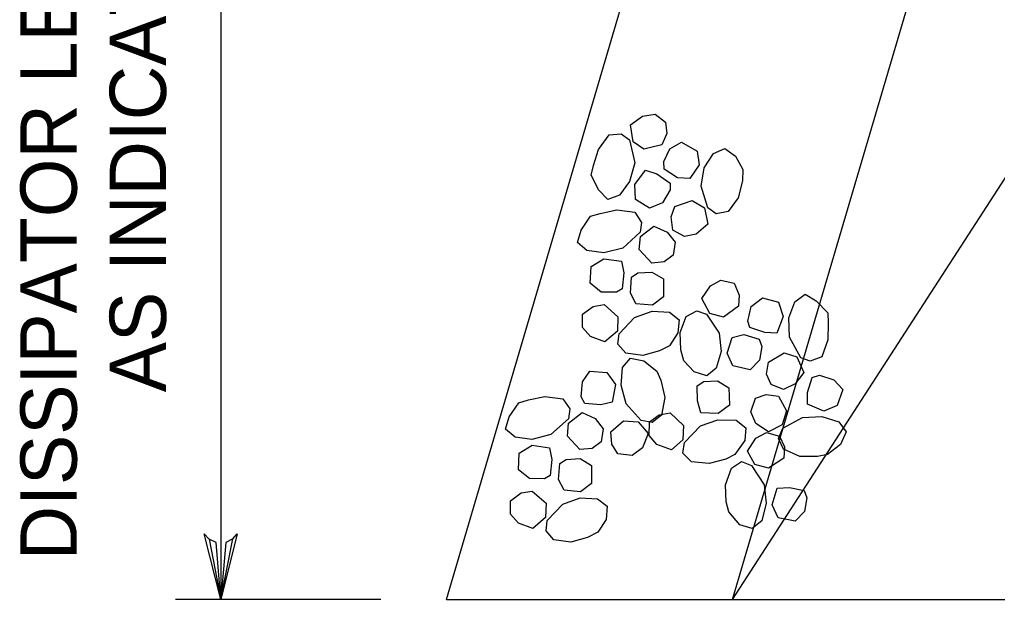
# Model space of a CAD drawing. Extents: x 636462 to 639890, y 299944 to 300538.
# Drawn here: x 637624.9 to 637676.9, y 300172.3 to 300203.1 of the extents above; entities that cross this region are included whole.
import ezdxf

# ---------------------------------------------------------------- set-up
doc = ezdxf.new("R2010")
doc.units = 0
doc.layers.add('Default', color=7, linetype='Continuous')

msp = doc.modelspace()

# ---------------------------------------------------------------- linework, layer by layer
at = {"layer": 'Default'}
for p, q in [((637635.644, 300227.091), (637635.644, 300172.26)), ((637647.635, 300172.26), (637663.777, 300227.091)), ((637662.855, 300172.26), (637698.264, 300227.091)), ((637662.855, 300172.26), (637678.997, 300227.091)), ((637658.054, 300197.981), (637658.728, 300198.086)), ((637658.728, 300198.086), (637659.28, 300197.665)), ((637657.432, 300197.527), (637658.054, 300197.981)), ((637657.563, 300196.629), (637657.432, 300197.527)), ((637659.28, 300197.665), (637659.359, 300197.065)), ((637656.287, 300196.995), (637656.936, 300197.049)), ((637656.936, 300197.049), (637657.363, 300196.727)), ((637659.359, 300197.065), (637659.088, 300196.464)), ((637655.717, 300196.216), (637656.287, 300196.995)), ((637657.363, 300196.727), (637657.646, 300195.505)), ((637658.141, 300196.233), (637657.563, 300196.629)), ((637659.515, 300196.242), (637660.137, 300196.596)), ((637660.137, 300196.596), (637660.965, 300196.127)), ((637655.448, 300195.365), (637655.717, 300196.216)), ((637659.088, 300196.464), (637658.141, 300196.233)), ((637659.194, 300195.565), (637659.515, 300196.242)), ((637660.965, 300196.127), (637661.069, 300195.403)), ((637661.345, 300195.23), (637661.84, 300196.008)), ((637661.84, 300196.008), (637662.438, 300196.262)), ((637662.438, 300196.262), (637663.015, 300195.866)), ((637657.646, 300195.505), (637657.378, 300194.504)), ((637659.222, 300195.166), (637659.194, 300195.565)), ((637663.015, 300195.866), (637663.395, 300195.144)), ((637655.327, 300194.84), (637655.448, 300195.365)), ((637657.654, 300194.356), (637658.223, 300195.109)), ((637658.223, 300195.109), (637658.824, 300194.913)), ((637659.925, 300194.696), (637659.222, 300195.166)), ((637661.069, 300195.403), (637660.575, 300194.675)), ((637661.177, 300194.254), (637661.345, 300195.23)), ((637663.395, 300195.144), (637663.374, 300194.544)), ((637655.732, 300194.043), (637655.327, 300194.84)), ((637657.378, 300194.504), (637656.833, 300193.776)), ((637658.824, 300194.913), (637659.527, 300194.418)), ((637659.527, 300194.418), (637659.529, 300194.068)), ((637660.575, 300194.675), (637659.925, 300194.696)), ((637663.374, 300194.544), (637663.155, 300193.643)), ((637656.21, 300193.546), (637655.732, 300194.043)), ((637657.684, 300193.556), (637657.654, 300194.356)), ((637659.529, 300194.068), (637659.134, 300193.366)), ((637661.534, 300193.108), (637661.177, 300194.254)), ((637656.833, 300193.776), (637656.21, 300193.546)), ((637658.437, 300193.087), (637657.684, 300193.556)), ((637659.134, 300193.366), (637658.437, 300193.087)), ((637659.785, 300193.171), (637660.707, 300193.502)), ((637660.707, 300193.502), (637661.36, 300193.106)), ((637663.155, 300193.643), (637662.61, 300192.915)), ((637655.816, 300192.812), (637656.691, 300192.992)), ((637656.691, 300192.992), (637657.648, 300192.875)), ((637657.648, 300192.875), (637658.012, 300192.335)), ((637659.589, 300192.62), (637659.785, 300193.171)), ((637661.36, 300193.106), (637661.54, 300192.233)), ((637661.986, 300192.786), (637661.534, 300193.108)), ((637662.61, 300192.915), (637661.986, 300192.786)), ((637654.801, 300191.919), (637655.299, 300192.662)), ((637655.299, 300192.662), (637655.816, 300192.812)), ((637658.012, 300192.335), (637657.939, 300191.805)), ((637659.669, 300191.921), (637659.589, 300192.62)), ((637654.6, 300191.26), (637654.801, 300191.919)), ((637657.939, 300191.805), (637657.01, 300190.962)), ((637657.951, 300191.582), (637658.672, 300192.134)), ((637658.672, 300192.134), (637659.371, 300191.813)), ((637659.371, 300191.813), (637659.791, 300191.276)), ((637660.296, 300191.575), (637659.669, 300191.921)), ((637661.54, 300192.233), (637660.919, 300191.704)), ((637657.887, 300190.885), (637657.951, 300191.582)), ((637660.919, 300191.704), (637660.296, 300191.575)), ((637655.104, 300190.828), (637654.6, 300191.26)), ((637656.006, 300190.707), (637655.104, 300190.828)), ((637657.01, 300190.962), (637656.006, 300190.707)), ((637658.551, 300190.17), (637657.887, 300190.885)), ((637659.791, 300191.276), (637659.693, 300190.588)), ((637655.328, 300189.978), (637656.011, 300190.394)), ((637656.011, 300190.394), (637656.947, 300190.265)), ((637656.947, 300190.265), (637657.069, 300189.644)), ((637659.693, 300190.588), (637659.209, 300190.227)), ((637655.285, 300189.092), (637655.328, 300189.978)), ((637659.209, 300190.227), (637658.551, 300190.17)), ((637657.069, 300189.644), (637656.98, 300188.789)), ((637657.416, 300188.577), (637657.483, 300189.42)), ((637657.483, 300189.42), (637657.819, 300189.639)), ((637657.819, 300189.639), (637658.566, 300189.69)), ((637658.566, 300189.69), (637659.178, 300189.319)), ((637659.178, 300189.319), (637659.172, 300188.368)), ((637661.67, 300188.96), (637662.233, 300189.258)), ((637662.233, 300189.258), (637662.931, 300189.101)), ((637655.87, 300188.619), (637655.285, 300189.092)), ((637656.98, 300188.789), (637656.675, 300188.617)), ((637661.221, 300188.279), (637661.67, 300188.96)), ((637662.931, 300189.101), (637663.203, 300188.452)), ((637656.675, 300188.617), (637655.87, 300188.619)), ((637657.715, 300188), (637657.416, 300188.577)), ((637659.172, 300188.368), (637658.592, 300187.923)), ((637661.638, 300187.491), (637661.221, 300188.279)), ((637663.203, 300188.452), (637663.168, 300187.868)), ((637663.848, 300187.862), (637664.44, 300188.325)), ((637664.44, 300188.325), (637665.293, 300188.084)), ((637666.172, 300188.111), (637666.706, 300188.505)), ((637666.706, 300188.505), (637667.304, 300188.162)), ((637654.868, 300187.447), (637655.44, 300187.858)), ((637655.44, 300187.858), (637656.016, 300187.955)), ((637656.016, 300187.955), (637656.755, 300187.312)), ((637658.592, 300187.923), (637657.715, 300188)), ((637663.168, 300187.868), (637662.375, 300187.293)), ((637663.664, 300187.078), (637663.848, 300187.862)), ((637665.293, 300188.084), (637665.546, 300187.325)), ((637665.852, 300187.26), (637666.172, 300188.111)), ((637667.304, 300188.162), (637667.915, 300187.51)), ((637654.873, 300186.732), (637654.868, 300187.447)), ((637656.755, 300187.312), (637656.728, 300186.55)), ((637656.815, 300186.398), (637657.641, 300187.269)), ((637657.641, 300187.269), (637658.575, 300187.598)), ((637658.575, 300187.598), (637659.495, 300187.546)), ((637659.495, 300187.546), (637660.009, 300187.148)), ((637660.009, 300187.148), (637659.945, 300186.451)), ((637660.064, 300186.475), (637660.384, 300187.326)), ((637660.384, 300187.326), (637660.947, 300187.624)), ((637660.947, 300187.624), (637661.471, 300187.441)), ((637661.471, 300187.441), (637662.134, 300186.439)), ((637662.375, 300187.293), (637661.638, 300187.491)), ((637665.546, 300187.325), (637665.209, 300186.443)), ((637665.874, 300186.224), (637665.852, 300187.26)), ((637667.915, 300187.51), (637667.945, 300186.971)), ((637655.29, 300186.25), (637654.873, 300186.732)), ((637663.764, 300186.743), (637663.664, 300187.078)), ((637664.577, 300186.463), (637663.764, 300186.743)), ((637667.945, 300186.971), (637667.924, 300186.079)), ((637656.054, 300185.966), (637655.29, 300186.25)), ((637656.728, 300186.55), (637656.054, 300185.966)), ((637656.754, 300185.846), (637656.815, 300186.398)), ((637659.945, 300186.451), (637659.5, 300185.767)), ((637660.105, 300185.548), (637660.064, 300186.475)), ((637662.134, 300186.439), (637662.244, 300185.456)), ((637662.558, 300185.367), (637662.83, 300186.204)), ((637662.83, 300186.204), (637663.459, 300186.365)), ((637663.459, 300186.365), (637664.265, 300186.11)), ((637664.265, 300186.11), (637664.403, 300185.734)), ((637665.209, 300186.443), (637664.577, 300186.463)), ((637666.487, 300185.129), (637665.874, 300186.224)), ((637657.171, 300185.365), (637656.754, 300185.846)), ((637659.5, 300185.767), (637658.966, 300185.493)), ((637664.403, 300185.734), (637664.285, 300184.995)), ((637667.924, 300186.079), (637667.595, 300185.172)), ((637656.995, 300184.601), (637657.427, 300185.105)), ((637658.073, 300185.244), (637657.171, 300185.365)), ((637657.427, 300185.105), (637658.14, 300184.963)), ((637658.966, 300185.493), (637658.073, 300185.244)), ((637660.252, 300184.967), (637660.105, 300185.548)), ((637662.244, 300185.456), (637661.987, 300184.571)), ((637662.86, 300184.701), (637662.558, 300185.367)), ((637664.756, 300184.9), (637665.602, 300185.387)), ((637665.602, 300185.387), (637666.266, 300185.168)), ((637666.266, 300185.168), (637666.643, 300184.342)), ((637666.986, 300184.939), (637666.487, 300185.129)), ((637667.595, 300185.172), (637666.986, 300184.939)), ((637656.921, 300183.668), (637656.995, 300184.601)), ((637658.14, 300184.963), (637658.829, 300184.407)), ((637660.818, 300184.379), (637660.252, 300184.967)), ((637661.987, 300184.571), (637661.483, 300184.16)), ((637663.786, 300184.481), (637662.86, 300184.701)), ((637664.285, 300184.995), (637663.786, 300184.481)), ((637664.664, 300184.247), (637664.756, 300184.9)), ((637654.864, 300183.851), (637655.259, 300184.42)), ((637655.259, 300184.42), (637656.17, 300184.334)), ((637656.17, 300184.334), (637656.618, 300183.697)), ((637658.829, 300184.407), (637659.045, 300183.926)), ((637661.483, 300184.16), (637660.818, 300184.379)), ((637664.907, 300183.694), (637664.664, 300184.247)), ((637666.643, 300184.342), (637666.173, 300183.732)), ((637666.83, 300183.276), (637667.085, 300184.082)), ((637667.085, 300184.082), (637667.468, 300184.196)), ((637667.468, 300184.196), (637668.243, 300183.958)), ((637654.806, 300183.042), (637654.864, 300183.851)), ((637656.618, 300183.697), (637656.454, 300182.771)), ((637657.197, 300182.676), (637656.921, 300183.668)), ((637659.045, 300183.926), (637659.25, 300183.008)), ((637660.962, 300183.635), (637661.319, 300183.867)), ((637660.981, 300182.842), (637660.962, 300183.635)), ((637661.319, 300183.867), (637662.044, 300183.905)), ((637662.044, 300183.905), (637662.657, 300183.534)), ((637662.657, 300183.534), (637662.694, 300182.608)), ((637665.555, 300183.444), (637664.907, 300183.694)), ((637666.173, 300183.732), (637665.555, 300183.444)), ((637668.243, 300183.958), (637668.709, 300183.445)), ((637651.995, 300182.883), (637652.869, 300183.063)), ((637652.869, 300183.063), (637653.826, 300182.946)), ((637655.003, 300182.695), (637654.806, 300183.042)), ((637659.25, 300183.008), (637659.064, 300182.07)), ((637663.825, 300182.251), (637664.077, 300182.978)), ((637664.077, 300182.978), (637664.645, 300183.173)), ((637664.645, 300183.173), (637665.298, 300183.081)), ((637665.298, 300183.081), (637665.715, 300182.293)), ((637666.833, 300182.652), (637666.83, 300183.276)), ((637668.709, 300183.445), (637668.42, 300182.577)), ((637650.979, 300181.99), (637651.477, 300182.733)), ((637651.477, 300182.733), (637651.995, 300182.883)), ((637653.826, 300182.946), (637654.191, 300182.406)), ((637655.846, 300182.627), (637655.003, 300182.695)), ((637656.454, 300182.771), (637655.846, 300182.627)), ((637657.994, 300181.778), (637657.197, 300182.676)), ((637661.172, 300182.203), (637660.981, 300182.842)), ((637662.694, 300182.608), (637662.092, 300182.151)), ((637667.699, 300182.284), (637666.833, 300182.652)), ((637668.42, 300182.577), (637667.699, 300182.284)), ((637650.779, 300181.331), (637650.979, 300181.99)), ((637654.191, 300182.406), (637654.118, 300181.876)), ((637654.13, 300181.653), (637654.85, 300182.205)), ((637654.85, 300182.205), (637655.549, 300181.884)), ((637658.434, 300181.712), (637658.94, 300182.085)), ((637659.064, 300182.07), (637658.57, 300181.674)), ((637658.94, 300182.085), (637659.539, 300182.195)), ((637659.539, 300182.195), (637660.234, 300181.527)), ((637662.092, 300182.151), (637661.172, 300182.203)), ((637664.089, 300181.626), (637663.825, 300182.251)), ((637665.715, 300182.293), (637665.494, 300181.549)), ((637665.52, 300181.374), (637666.574, 300181.949)), ((637666.574, 300181.949), (637667.603, 300181.994)), ((637667.603, 300181.994), (637668.495, 300181.713)), ((637654.118, 300181.876), (637653.189, 300181.033)), ((637654.066, 300180.956), (637654.13, 300181.653)), ((637655.549, 300181.884), (637655.969, 300181.347)), ((637656.381, 300181.179), (637657.055, 300181.762)), ((637657.055, 300181.762), (637657.83, 300181.714)), ((637657.83, 300181.714), (637658.355, 300181.092)), ((637658.57, 300181.674), (637657.994, 300181.778)), ((637658.416, 300180.984), (637658.434, 300181.712)), ((637660.234, 300181.527), (637660.207, 300180.765)), ((637660.293, 300180.613), (637661.142, 300181.497)), ((637661.142, 300181.497), (637662.075, 300181.825)), ((637662.075, 300181.825), (637663.039, 300181.798)), ((637663.039, 300181.798), (637663.552, 300181.4)), ((637664.77, 300181.177), (637664.089, 300181.626)), ((637665.494, 300181.549), (637664.77, 300181.177)), ((637668.495, 300181.713), (637668.889, 300181.178)), ((637651.283, 300180.899), (637650.779, 300181.331)), ((637652.184, 300180.778), (637651.283, 300180.899)), ((637653.189, 300181.033), (637652.184, 300180.778)), ((637654.73, 300180.241), (637654.066, 300180.956)), ((637655.969, 300181.347), (637655.871, 300180.659)), ((637656.438, 300180.521), (637656.381, 300181.179)), ((637658.355, 300181.092), (637658.071, 300180.328)), ((637658.833, 300180.502), (637658.416, 300180.984)), ((637663.552, 300181.4), (637663.51, 300180.715)), ((637664.088, 300180.843), (637664.651, 300181.141)), ((637664.651, 300181.141), (637665.356, 300180.96)), ((637665.289, 300180.836), (637665.52, 300181.374)), ((637665.356, 300180.96), (637665.606, 300180.383)), ((637668.889, 300181.178), (637668.591, 300180.516)), ((637651.506, 300180.049), (637652.189, 300180.465)), ((637652.189, 300180.465), (637653.125, 300180.336)), ((637655.871, 300180.659), (637655.387, 300180.298)), ((637656.756, 300180.012), (637656.438, 300180.521)), ((637659.598, 300180.218), (637658.833, 300180.502)), ((637660.207, 300180.765), (637659.598, 300180.218)), ((637660.211, 300180.049), (637660.293, 300180.613)), ((637663.51, 300180.715), (637662.978, 300179.982)), ((637663.639, 300180.162), (637664.088, 300180.843)), ((637665.563, 300180.266), (637665.289, 300180.836)), ((637665.606, 300180.383), (637665.579, 300179.775)), ((637668.591, 300180.516), (637667.893, 300179.969)), ((637651.464, 300179.163), (637651.506, 300180.049)), ((637653.125, 300180.336), (637653.247, 300179.715)), ((637655.387, 300180.298), (637654.73, 300180.241)), ((637657.521, 300179.93), (637656.756, 300180.012)), ((637658.071, 300180.328), (637657.521, 300179.93)), ((637660.672, 300179.592), (637660.211, 300180.049)), ((637662.978, 300179.982), (637662.488, 300179.733)), ((637664.035, 300179.446), (637663.639, 300180.162)), ((637666.436, 300179.874), (637665.563, 300180.266)), ((637667.376, 300179.868), (637666.436, 300179.874)), ((637667.893, 300179.969), (637667.376, 300179.868)), ((637653.247, 300179.715), (637653.158, 300178.86)), ((637653.594, 300178.648), (637653.662, 300179.491)), ((637653.662, 300179.491), (637653.997, 300179.71)), ((637653.997, 300179.71), (637654.744, 300179.761)), ((637654.744, 300179.761), (637655.356, 300179.39)), ((637655.356, 300179.39), (637655.351, 300178.439)), ((637661.616, 300179.496), (637660.672, 300179.592)), ((637662.488, 300179.733), (637661.616, 300179.496)), ((637662.787, 300179.257), (637663.336, 300179.603)), ((637663.336, 300179.603), (637663.867, 300179.396)), ((637663.867, 300179.396), (637664.537, 300178.37)), ((637664.771, 300179.248), (637664.035, 300179.446)), ((637665.579, 300179.775), (637664.771, 300179.248)), ((637652.048, 300178.69), (637651.464, 300179.163)), ((637653.158, 300178.86), (637652.854, 300178.688)), ((637662.482, 300178.358), (637662.787, 300179.257)), ((637652.854, 300178.688), (637652.048, 300178.69)), ((637653.893, 300178.071), (637653.594, 300178.648)), ((637655.351, 300178.439), (637654.77, 300177.994)), ((637662.516, 300177.455), (637662.482, 300178.358)), ((637664.537, 300178.37), (637664.648, 300177.387)), ((637651.047, 300177.518), (637651.618, 300177.929)), ((637651.618, 300177.929), (637652.195, 300178.026)), ((637652.195, 300178.026), (637652.934, 300177.383)), ((637654.77, 300177.994), (637653.893, 300178.071)), ((637664.961, 300177.297), (637665.219, 300178.182)), ((637665.219, 300178.182), (637665.884, 300178.224)), ((637665.884, 300178.224), (637666.662, 300178.065)), ((637666.662, 300178.065), (637666.807, 300177.665)), ((637651.051, 300176.803), (637651.047, 300177.518)), ((637652.934, 300177.383), (637652.907, 300176.621)), ((637652.993, 300176.469), (637653.82, 300177.34)), ((637653.82, 300177.34), (637654.753, 300177.669)), ((637654.753, 300177.669), (637655.674, 300177.617)), ((637655.674, 300177.617), (637656.187, 300177.219)), ((637662.649, 300176.921), (637662.516, 300177.455)), ((637664.648, 300177.387), (637664.404, 300176.454)), ((637665.271, 300176.608), (637664.961, 300177.297)), ((637666.807, 300177.665), (637666.681, 300176.949)), ((637651.468, 300176.321), (637651.051, 300176.803)), ((637656.187, 300177.219), (637656.123, 300176.522)), ((637663.243, 300176.238), (637662.649, 300176.921)), ((637666.681, 300176.949), (637666.182, 300176.436)), ((637652.233, 300176.037), (637651.468, 300176.321)), ((637652.907, 300176.621), (637652.233, 300176.037)), ((637652.933, 300175.917), (637652.993, 300176.469)), ((637656.123, 300176.522), (637655.678, 300175.838)), ((637663.901, 300176.043), (637663.243, 300176.238)), ((637664.404, 300176.454), (637663.901, 300176.043)), ((637666.182, 300176.436), (637665.271, 300176.608)), ((637653.35, 300175.436), (637652.933, 300175.917)), ((637655.678, 300175.838), (637655.144, 300175.564)), ((637654.251, 300175.315), (637653.35, 300175.436)), ((637655.144, 300175.564), (637654.251, 300175.315)), ((637644.139, 300172.26), (637633.225, 300172.26)), ((637647.635, 300172.26), (637781.846, 300172.26))]:
    msp.add_line(p, q, dxfattribs=at)
msp.add_lwpolyline([(637636.281, 300175.492), (637636.504, 300175.761), (637635.644, 300172.26), (637636.281, 300175.492), (637635.908, 300175.295), (637635.644, 300172.26), (637635.385, 300175.289), (637635.009, 300175.471), (637635.644, 300172.26), (637634.755, 300175.754), (637635.009, 300175.471)], dxfattribs=at)

# ---------------------------------------------------------------- texts
for s, p in [('DISSIPATOR LENGTH,', (637627.976, 300174.343)), ('AS INDICATED', (637632.723, 300183.29))]:
    msp.add_text(s, height=2.99804, rotation=90, dxfattribs=at).set_placement(p)

doc.saveas('drawing.dxf')
